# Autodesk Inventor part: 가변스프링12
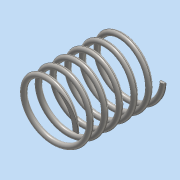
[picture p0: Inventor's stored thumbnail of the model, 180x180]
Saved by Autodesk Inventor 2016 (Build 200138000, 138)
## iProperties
Created: 2018-11
Part Number: 가변스프링12
Material: 스테인레스 스틸
Document SubType Name: Modeling
Designer: user
Density: 8 g/cm^3
Appearance: 반연마
Mass: 84.1985 g
Surface Area: 106.475 cm^2
Volume: 10.5248 cm^3
Author: user
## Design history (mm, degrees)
sketch "스케치1"
  geometry: L1 (0, 0)-(22.5, 0); L2 (22.5, 0)-(22.5, 67.25); L3 (22.5, 67.25)-(0, 67.25); L4 (0, 67.25)-(0, 0); C1 r 2 at (22.5, 0)
  constraints: 8 end point, 2 parallel, 1 centre point, 1 coincident, 1 horizontal, 1 perpendicular
  dimensions: "d0" = 4 diameter of C1; "d1" = 45 diameter of L2 L4; "d2" = 67.25 distance of L1.end L2.end (derived)
feature "코일1" sketch "스케치1" pitch "d3" = 10; turns "d5" = 6; dims "d4" = 67.25 (= d2), "d6" = 0, angle "d7" = 90 deg, angle "d8" = 90 deg, "d9" = 0, "d10" = 0
sketch "스케치2"
  geometry: L1 (-48.29, 0)-(48.29, 0); L2 (48.29, 0)-(48.29, 67.25); L3 (48.29, 67.25)-(-48.29, 67.25); L4 (-48.29, 67.25)-(-48.29, 0); 2 further points
  constraints: 8 end point, 2 parallel, 1 coincident, 1 horizontal, 1 midpoint, 1 perpendicular
  dimensions: "d11" = 96.58086 distance of L2.end L3.end; "d12" = 67.25 distance of L1.end L2.end (= d2)
extrude "돌출1" sketch "스케치2" stored distance "d13" = 100; taper "d14" = 0 deg
node "솔리드1"
